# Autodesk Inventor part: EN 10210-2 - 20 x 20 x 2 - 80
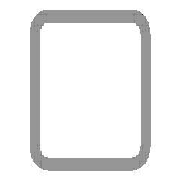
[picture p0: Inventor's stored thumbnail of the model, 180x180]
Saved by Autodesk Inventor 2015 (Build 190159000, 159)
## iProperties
Created: 2015-05
Part Number: EN 10210-2 - 20 x 20 x 2 - 80
Material: Steel, Mild
Description: Tube
Document SubType Name: Modeling
Standard: DIN
Designer: TREINA6
Standard Revision: 1997
Standards Organization: DIN
Language: en-US
Size Designation: 20 x 20 x 2
Categories: <MemberInstance><Categories><Category DisplayName="Structural Shapes" InternalName="089c4875-fa83-4c05-b084-43b9cc11f5ed" Mnemonic="GRDR"><CategoryParameter Dis
Stock Number: 20 x 20 x 2
Density: 7.85 g/cm^3
Appearance: Semi-Polished
IsCustomPart: 1
G_L: 80,000 mm
G_W: 20,000 mm
G_H: 20,000 mm
+2D132149-0D61-434C-8104-051B9A5C6C44+CUTDETAIL1: Cut
_CCFamilyMember: 1
_CCFamilyDisplayName: DIN EN 10210-2 (Square) - Tube
_FrameMemberDoc: Frame Member File
_Version: 15.0.0
_GetPNFromCC: 1
Author: TREINA6
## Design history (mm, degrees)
node "Start plane"
node "End plane"
sketch "Sketch"
  geometry: L1 (-10, -7)-(-10, 7); L2 (-7, 10)-(7, 10); L3 (10, 7)-(10, -7); L4 (7, -10)-(-7, -10); L5 (-7, 8)-(7, 8); L6 (8, 7)-(8, -7); L7 (7, -8)-(-7, -8); L8 (-8, -7)-(-8, 7); L9 (0, 14.87)-(0, -14.87) reference; L10 (-14.87, 0)-(14.87, 0) reference; A1 r 3 centre (-7, -7) between (-10, -7) and (-7, -10); A2 r 3 centre (-7, 7) between (-7, 10) and (-10, 7); A3 r 3 centre (7, 7) between (10, 7) and (7, 10); A4 r 3 centre (7, -7) between (7, -10) and (10, -7); A5 r 1 centre (-7, 7) between (-7, 8) and (-8, 7); A6 r 1 centre (7, 7) between (8, 7) and (7, 8); A7 r 1 centre (7, -7) between (7, -8) and (8, -7); A8 r 1 centre (-7, -7) between (-8, -7) and (-7, -8)
  constraints: 16 end point, 16 point on circle, 8 centre point, 8 tangent, 4 parallel, 3 equal radius, 2 perpendicular, 7 other
  dimensions: "d7" = 3 radius of A1 (= G_IR); "d10" = 20 distance between parallel lines of L2 L4 (= G_H); "d11" = 20 distance between parallel lines of L1 L3 (= G_W); "d12" = 2 distance between parallel lines of L3 L6 (= G_T); "d15" = 10 distance between parallel lines of L2 L10 (= 0.5 x d10); "d16" = 10 distance between parallel lines of L9 L3 (= 0.5 x d11)
extrude "Body" new body sketch "Sketch" stored distance "d3" = 80 (= G_L); taper "d4" = 0 deg
node "Driven Length"
  sketch "Sketch3"
    geometry: L1 (0, 0)-(10, 0) reference
    constraints: 2 end point, 1 horizontal
  workplane "Work Plane3"
  sketch "Sketch4"
    geometry: L1 (-2, 20)-(12, 20) reference; L2 (-2, 100)-(12, 100) reference
    dimensions: "d18" = 80 distance between parallel lines of L1 L2 (derived)
workplane "Work Plane4"
split "Split1"
body "Solid1"
other parameters: "G_W" = 20 [user parameter; used in 1 equation term], "G_H" = 20 [user parameter; used in 1 equation term], "G_T" = 2 [user parameter; used in 1 equation term], "G_IR" = 3 [user parameter; used in 1 equation term], "G_L" = 80 (= d18) [user parameter; used in 1 equation term], "G_OFFSET_END" = 0 [user parameter; used in 1 equation term], "d17" = 90 deg
